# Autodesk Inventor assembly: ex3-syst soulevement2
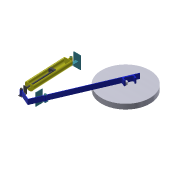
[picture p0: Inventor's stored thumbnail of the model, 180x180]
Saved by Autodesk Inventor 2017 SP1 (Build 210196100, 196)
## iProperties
Part Number: ex3-syst soulevement2
Material: Générique
Document SubType Name: Assembly
Designer: TJ
Author: TJ
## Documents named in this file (6)
- H:\Consmec\TSsi\02-Cours\02-02-Cinematique\02-02-02-Cinematique graphique\02-02-02-03-Composition des Vitesses\02-02-02-03-02-ExercicesCompoVit\02-02-02-03-02-03-Exercice3CompVit\02-02-02-03-02-03-02-Dessin SystSoulevement\ex3-syst soulevement2.iam
- H:\Consmec\TSsi\02-Cours\02-02-Cinematique\02-02-02-Cinematique graphique\02-02-02-03-Composition des Vitesses\02-02-02-03-02-ExercicesCompoVit\02-02-02-03-02-03-Exercice3CompVit\02-02-02-03-02-03-02-Dessin SystSoulevement\Pièce5.ipt
- H:\Consmec\TSsi\02-Cours\02-02-Cinematique\02-02-02-Cinematique graphique\02-02-02-03-Composition des Vitesses\02-02-02-03-02-ExercicesCompoVit\02-02-02-03-02-03-Exercice3CompVit\02-02-02-03-02-03-02-Dessin SystSoulevement\Pièce3.ipt
- H:\Consmec\TSsi\02-Cours\02-02-Cinematique\02-02-02-Cinematique graphique\02-02-02-03-Composition des Vitesses\02-02-02-03-02-ExercicesCompoVit\02-02-02-03-02-03-Exercice3CompVit\02-02-02-03-02-03-02-Dessin SystSoulevement\Pièce4.ipt
- H:\Consmec\TSsi\02-Cours\02-02-Cinematique\02-02-02-Cinematique graphique\02-02-02-03-Composition des Vitesses\02-02-02-03-02-ExercicesCompoVit\02-02-02-03-02-03-Exercice3CompVit\02-02-02-03-02-03-02-Dessin SystSoulevement\Pièce2.ipt
- H:\Consmec\TSsi\02-Cours\02-02-Cinematique\02-02-02-Cinematique graphique\02-02-02-03-Composition des Vitesses\02-02-02-03-02-ExercicesCompoVit\02-02-02-03-02-03-Exercice3CompVit\02-02-02-03-02-03-02-Dessin SystSoulevement\Pièce1.ipt
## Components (6 placed, 5 different names)
1. Pièce5:1 — Logement:1, Angle:2, Angle:3
2. Pièce5:2 — Logement:3, Angle:3
3. Pièce3:1 — Logement:1, Placage:1, Angle:1, Placage:2
4. Pièce4:1 — Placage:1, Angle:1, Logement:2, Angle:2, Placage:2
5. Pièce2:1 — Logement:2, Logement:3, Logement:4
6. Pièce1:1 — Logement:4
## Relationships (9: Insert 4, Angle 3, Mate 2)
- Logement:1 [Insert]: Pièce5:1 ↔ Pièce3:1
- Placage:1 [Mate]: Pièce3:1 ↔ Pièce4:1
- Angle:1: Pièce3:1 ↔ Pièce4:1
- Logement:2 [Insert]: Pièce4:1 ↔ Pièce2:1
- Angle:2: Pièce5:1 ↔ Pièce4:1
- Logement:3 [Insert]: Pièce5:2 ↔ Pièce2:1
- Angle:3: Pièce5:1 ↔ Pièce5:2
- Logement:4 [Insert]: Pièce2:1 ↔ Pièce1:1
- Placage:2 [Mate]: Pièce3:1 ↔ Pièce4:1
